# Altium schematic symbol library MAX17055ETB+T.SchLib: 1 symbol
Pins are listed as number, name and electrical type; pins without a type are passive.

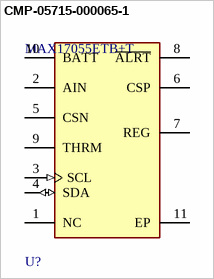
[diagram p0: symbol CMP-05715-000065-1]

## CMP-05715-000065-1
designator U?, comment MAX17055ETB+T
IC FUEL GAUGE MODELGAUGE 10TDFN; Manufacturer: Maxim Integrated; Nominal Supply Current: 18uA; Standoff Height: 0mm; Max Supply Voltage: 4.9V; Min Supply Voltage: 2.3V; Number Of Cells: 1
footprint FP-T102A2-1C-IPC_A
footprint FP-T102A2-1C-IPC_B
footprint FP-T102A2-1C-IPC_C
footprint FP-T102A2-1C-MFG
pins: 1 NC, 2 AIN, 3 SCL (in), 4 SDA (io), 5 CSN, 6 CSP (power), 7 REG (power), 8 ~{ALRT} (oc), 9 THRM, 10 BATT (power), 11 EP (power)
